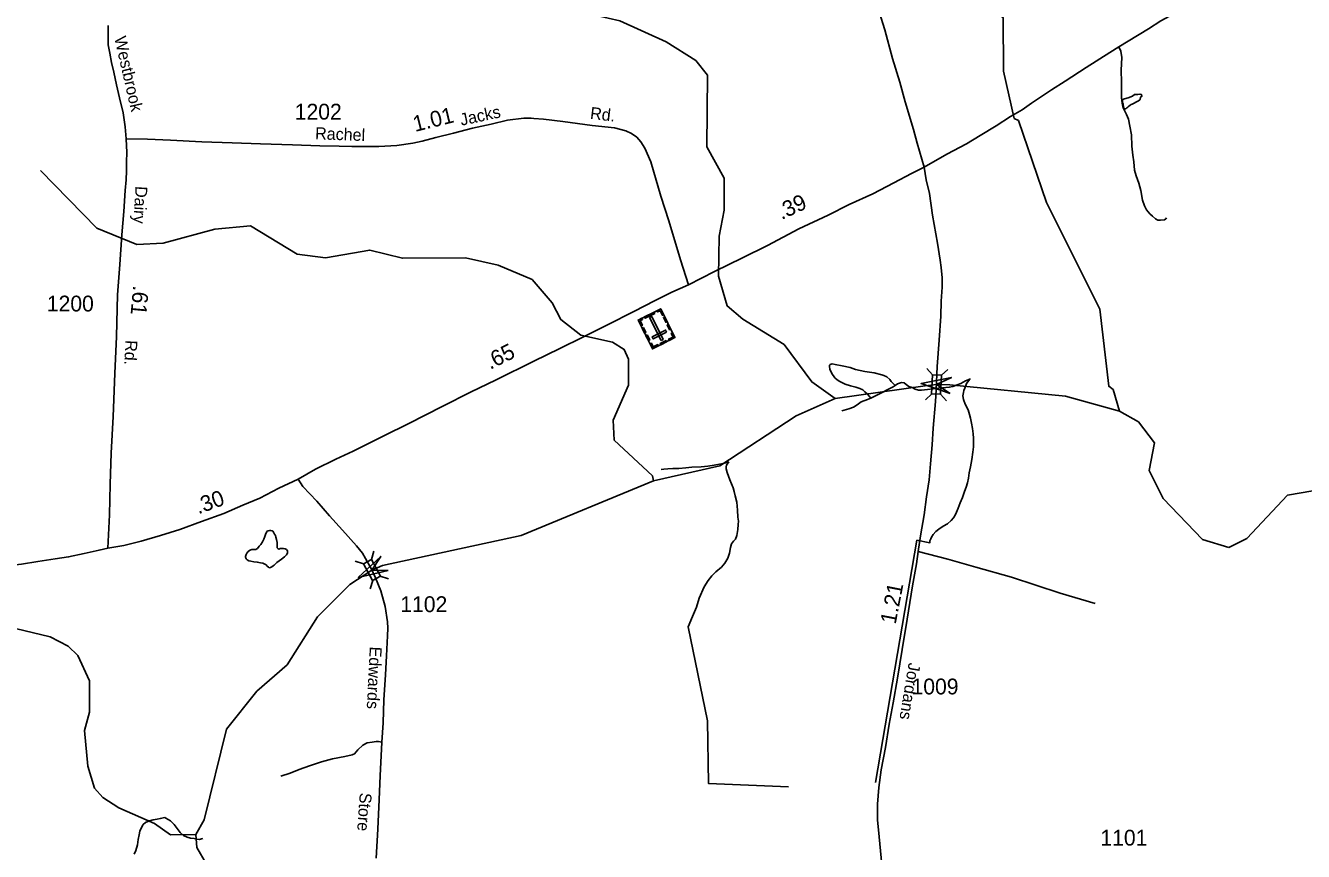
# Model space of a CAD drawing. Extents: x 2206922 to 2357709, y 510027 to 673830.
# Drawn here: x 2214408 to 2224516, y 553694 to 560227 of the extents above; entities that cross this region are included whole.
import ezdxf

# ---------------------------------------------------------------- set-up
doc = ezdxf.new("R2010")
doc.units = 0
for name, color, linetype in [('Exist Cultural Cemetery CELL', 7, 'Continuous'), ('Exist Hydrographic Creek Single Shore', 7, 'Continuous'), ('Exist Hydrographic Misc Water Feature', 7, 'Continuous'), ('Exist Road Non-System Type 51', 7, 'Continuous'), ('Exist Road Primary US Attributed', 7, 'Continuous'), ('Exist Road Primary US Mileage Hundredths English Label', 7, 'Continuous'), ('Exist Road Secondary Mileage Hundredths English Label', 7, 'Continuous'), ('Exist Road Secondary Structure Standard Bridge Attributed CELL', 7, 'Continuous'), ('Exist Road Secondary Structure Standard Bridge CELL', 7, 'Continuous'), ('Exist Road Secondary Type 51 Attributed', 7, 'Continuous'), ('Exist Road Secondary Type 51 Label', 7, 'Continuous'), ('Exist Road Secondary Type 51 Number Label', 7, 'Continuous')]:
    doc.layers.add(name, color=color, linetype=linetype)

msp = doc.modelspace()

# ---------------------------------------------------------------- linework, layer by layer
at = {"layer": 'Exist Cultural Cemetery CELL'}
for points in [[(2219545, 557758), (2219367, 557669), (2219253, 557897), (2219432, 557986)], [(2219402, 557971), (2219407, 557961), (2219427, 557971), (2219445, 557935), (2219455, 557940), (2219432, 557986)], [(2219283, 557912), (2219288, 557902), (2219269, 557892), (2219287, 557856), (2219277, 557851), (2219253, 557897)], [(2219385, 557950), (2219309, 557912), (2219304, 557922), (2219380, 557960)], [(2219435, 557736), (2219451, 557744), (2219361, 557926), (2219344, 557917)], [(2219463, 557924), (2219482, 557885), (2219472, 557880), (2219453, 557918)], [(2219296, 557838), (2219315, 557799), (2219305, 557794), (2219286, 557832)], [(2219478, 557801), (2219470, 557818), (2219365, 557765), (2219373, 557748)], [(2219493, 557863), (2219512, 557825), (2219502, 557820), (2219483, 557858)], [(2219526, 557797), (2219516, 557792), (2219530, 557763), (2219494, 557745), (2219499, 557735), (2219545, 557758)], [(2219325, 557779), (2219345, 557740), (2219335, 557735), (2219315, 557773)], [(2219348, 557708), (2219358, 557713), (2219372, 557684), (2219409, 557703), (2219414, 557693), (2219367, 557669)], [(2219479, 557725), (2219433, 557702), (2219428, 557712), (2219474, 557735)]]:
    msp.add_lwpolyline(points, close=True, dxfattribs=at)
at = {"layer": 'Exist Hydrographic Creek Single Shore'}
for points in [[(2223061, 557176), (2223010, 557347), (2222976, 557374), (2222906, 557982), (2222483, 558827), (2222262, 559475), (2222229, 559492), (2222143, 559867), (2222140, 560291), (2222115, 560307), (2222063, 560508), (2221970, 560691), (2221715, 561470), (2221680, 561713), (2221671, 561871), (2221646, 561895), (2221448, 562768), (2221212, 563117)], [(2223061, 557176), (2222635, 557296), (2221720, 557385), (2221613, 557386), (2221525, 557378), (2220811, 557277)], [(2223926, 556099), (2224069, 556168), (2224391, 556513), (2224590, 556545), (2225058, 556374), (2225391, 556420), (2225573, 556528), (2225987, 556848), (2226593, 557196), (2226824, 557405)], [(2219375, 556624), (2219899, 556744), (2220504, 557139), (2220811, 557277)], [(2223926, 556099), (2223718, 556162), (2223407, 556486), (2223297, 556708), (2223337, 556927), (2223211, 557091), (2223061, 557176)], [(2215754, 553827), (2215820, 553943), (2215998, 554661), (2216238, 554962), (2216478, 555170), (2216717, 555549), (2216973, 555806), (2217147, 555918), (2217230, 555956), (2218328, 556192), (2219375, 556624)], [(2211696, 554498), (2212025, 554650), (2212828, 555394), (2213144, 555532), (2213584, 555635), (2214001, 555577), (2214327, 555456), (2214602, 555392), (2214744, 555317), (2214820, 555243), (2214913, 555044), (2214914, 554795), (2214874, 554651), (2214901, 554369), (2214952, 554194), (2215019, 554120), (2215145, 554039), (2215429, 553915), (2215554, 553824), (2215754, 553827)], [(2215672, 549578), (2216199, 549646), (2216399, 549724), (2216523, 549800), (2216614, 549959), (2216638, 550116), (2216612, 550198), (2216528, 550282), (2216044, 550495), (2215910, 550576), (2215809, 550769), (2215814, 551202), (2215896, 551311), (2216103, 551511), (2216210, 551705), (2216209, 551912), (2216099, 552160), (2216080, 552544), (2216160, 552930), (2216142, 553147), (2216083, 553302), (2215839, 553592), (2215763, 553725), (2215754, 553827)]]:
    msp.add_lwpolyline(points, dxfattribs=at)
at = {"layer": 'Exist Hydrographic Misc Water Feature'}
for points in [[(2220811, 557277), (2220627, 557408), (2220408, 557705), (2220082, 557905), (2219957, 558009), (2219888, 558243), (2219895, 558561), (2219935, 558767), (2219933, 559020), (2219798, 559268), (2219802, 559833), (2219710, 559949), (2219476, 560098), (2219108, 560263), (2218833, 560328), (2218241, 560323), (2217925, 560353), (2217641, 560470), (2217440, 560608), (2216730, 560872), (2216488, 560995), (2216018, 561441), (2215984, 561497)], [(2223090, 559607), (2223086, 559619), (2223084, 559631), (2223084, 559641), (2223100, 559647), (2223129, 559655), (2223165, 559667), (2223181, 559680), (2223207, 559682), (2223221, 559684), (2223231, 559682), (2223235, 559682), (2223239, 559668), (2223228, 559660), (2223225, 559642), (2223223, 559638), (2223211, 559630), (2223206, 559628), (2223190, 559621), (2223176, 559613), (2223162, 559605), (2223154, 559603), (2223146, 559597), (2223134, 559589), (2223128, 559581), (2223118, 559575), (2223112, 559569), (2223104, 559569), (2223098, 559571), (2223092, 559581), (2223090, 559607)], [(2219375, 556624), (2219366, 556666), (2219064, 556948), (2219055, 557106), (2219178, 557382), (2219177, 557589), (2219143, 557665), (2219051, 557722), (2218800, 557777), (2218641, 557901), (2218574, 558034), (2218414, 558217), (2218147, 558331), (2217888, 558389), (2217389, 558386), (2217130, 558450), (2216780, 558388), (2216555, 558419), (2216187, 558643), (2215904, 558616), (2215497, 558506), (2215289, 558494), (2214971, 558625), (2214527, 559080)], [(2221286, 557379), (2221256, 557411), (2221244, 557427), (2221220, 557447), (2221198, 557459), (2221180, 557465), (2221120, 557480), (2221047, 557490), (2220973, 557507), (2220931, 557521), (2220867, 557535), (2220811, 557546), (2220789, 557550), (2220773, 557546), (2220767, 557540), (2220767, 557530), (2220771, 557508), (2220786, 557474), (2220810, 557440), (2220828, 557424), (2220848, 557412), (2220866, 557403), (2220892, 557391), (2220932, 557377), (2220976, 557365), (2221006, 557356), (2221030, 557344), (2221047, 557330), (2221067, 557312), (2221093, 557278)], [(2221132, 554240), (2221459, 556155), (2221561, 556136), (2221562, 556152), (2221568, 556166), (2221573, 556180), (2221586, 556202), (2221608, 556224), (2221632, 556243), (2221666, 556267), (2221701, 556285), (2221729, 556311), (2221749, 556333), (2221761, 556353), (2221771, 556377), (2221786, 556409), (2221800, 556452), (2221818, 556493), (2221835, 556542), (2221847, 556574), (2221859, 556610), (2221867, 556646), (2221871, 556688), (2221882, 556736), (2221892, 556794), (2221901, 556852), (2221905, 556894), (2221907, 556934), (2221907, 556962), (2221904, 556998), (2221898, 557038), (2221890, 557082), (2221882, 557120), (2221875, 557150), (2221863, 557188), (2221841, 557233), (2221827, 557269), (2221822, 557297), (2221826, 557324), (2221830, 557341), (2221838, 557359), (2221852, 557395), (2221877, 557430), (2221881, 557436)], [(2221286, 557379), (2221306, 557392), (2221338, 557402), (2221358, 557400), (2221374, 557386), (2221396, 557372), (2221420, 557363), (2221444, 557351), (2221470, 557343), (2221496, 557343), (2221542, 557347), (2221588, 557354), (2221628, 557358), (2221662, 557362), (2221714, 557366), (2221744, 557371), (2221778, 557385), (2221806, 557395), (2221842, 557415), (2221877, 557430), (2221881, 557436)], [(2221093, 557278), (2221109, 557286), (2221183, 557323), (2221224, 557345), (2221272, 557369), (2221286, 557379)], [(2220865, 557179), (2220884, 557185), (2220920, 557195), (2220957, 557207), (2220985, 557227), (2221019, 557250), (2221067, 557268), (2221093, 557278)], [(2219436, 556715), (2219458, 556717), (2219489, 556720), (2219529, 556722), (2219575, 556724), (2219631, 556729), (2219678, 556733), (2219751, 556735), (2219805, 556742), (2219855, 556750), (2219925, 556762), (2219971, 556775)], [(2220442, 554205), (2219811, 554231), (2219801, 554728), (2219648, 555471), (2219683, 555551), (2219715, 555626), (2219736, 555698), (2219776, 555788), (2219807, 555836), (2219837, 555874), (2219869, 555906), (2219913, 555943), (2219940, 555975), (2219962, 556013), (2219976, 556053), (2219983, 556099), (2219993, 556127), (2220007, 556147), (2220023, 556163), (2220033, 556192), (2220043, 556240), (2220046, 556279), (2220048, 556306), (2220042, 556339), (2220040, 556393), (2220035, 556457), (2220021, 556507), (2220012, 556541), (2220004, 556569), (2219980, 556633), (2219958, 556691), (2219951, 556719), (2219951, 556735), (2219953, 556749), (2219971, 556775)], [(2216396, 555978), (2216384, 555968), (2216374, 555958), (2216366, 555952), (2216357, 555944), (2216350, 555942), (2216346, 555940), (2216336, 555938), (2216330, 555942), (2216320, 555950), (2216310, 555960), (2216296, 555968), (2216284, 555974), (2216266, 555977), (2216240, 555983), (2216214, 555985), (2216190, 555989), (2216174, 555993), (2216160, 556001), (2216152, 556007), (2216150, 556015), (2216148, 556021), (2216148, 556027), (2216150, 556035), (2216154, 556043), (2216159, 556053), (2216169, 556065), (2216180, 556073), (2216189, 556079), (2216197, 556081), (2216213, 556081), (2216221, 556081), (2216229, 556083), (2216237, 556087), (2216243, 556091), (2216257, 556108), (2216269, 556122), (2216281, 556142), (2216293, 556163), (2216301, 556184), (2216309, 556210), (2216316, 556222), (2216320, 556228), (2216328, 556230), (2216338, 556232), (2216348, 556232), (2216358, 556230), (2216364, 556226), (2216368, 556218), (2216376, 556204), (2216384, 556192), (2216388, 556180), (2216393, 556162), (2216397, 556138), (2216399, 556124), (2216399, 556108), (2216397, 556100), (2216399, 556094), (2216405, 556088), (2216413, 556086), (2216423, 556089), (2216435, 556091), (2216449, 556089), (2216461, 556087), (2216471, 556081), (2216479, 556071), (2216481, 556063), (2216480, 556053), (2216475, 556045), (2216472, 556039), (2216455, 556025), (2216432, 556005), (2216396, 555978)], [(2215268, 553672), (2215280, 553700), (2215292, 553746), (2215299, 553788), (2215307, 553826), (2215313, 553854), (2215321, 553878), (2215337, 553906), (2215357, 553922), (2215388, 553935), (2215418, 553943), (2215449, 553949), (2215473, 553953), (2215510, 553961)], [(2215510, 553961), (2215518, 553957), (2215553, 553935), (2215583, 553906), (2215607, 553874), (2215631, 553844), (2215657, 553820), (2215687, 553806), (2215713, 553799), (2215741, 553795), (2215762, 553791), (2215782, 553789), (2215809, 553797)]]:
    msp.add_lwpolyline(points, dxfattribs=at)
at = {"layer": 'Exist Road Non-System Type 51'}
for points in [[(2223056, 560057), (2223073, 560024), (2223080, 559974), (2223075, 559874), (2223076, 559779), (2223076, 559686), (2223077, 559656), (2223080, 559633), (2223082, 559612), (2223087, 559587), (2223093, 559571), (2223116, 559523), (2223132, 559486), (2223144, 559432), (2223155, 559363), (2223160, 559273), (2223167, 559201), (2223174, 559148), (2223181, 559082), (2223192, 559038), (2223213, 558981), (2223231, 558923), (2223244, 558846), (2223259, 558801), (2223276, 558769), (2223300, 558738), (2223322, 558719), (2223346, 558697), (2223364, 558688), (2223386, 558687), (2223416, 558690), (2223428, 558699), (2223433, 558706)], [(2221468, 556067), (2221702, 556006), (2221926, 555942), (2222207, 555862), (2222591, 555738), (2222868, 555654)], [(2217227, 554557), (2217199, 554564), (2217180, 554563), (2217150, 554559), (2217110, 554553), (2217075, 554535), (2217035, 554498), (2217010, 554467), (2216992, 554458), (2216933, 554444), (2216837, 554427), (2216749, 554403), (2216653, 554370), (2216571, 554343), (2216501, 554312), (2216428, 554288)]]:
    msp.add_lwpolyline(points, dxfattribs=at)
at = {"layer": 'Exist Road Primary US Attributed'}
for points in [[(2221517, 559106), (2221695, 559208), (2221851, 559292), (2221960, 559358), (2222086, 559434), (2222198, 559507), (2222291, 559560), (2222366, 559613), (2222435, 559660), (2222524, 559718), (2222632, 559786), (2222798, 559896), (2222986, 560013), (2223056, 560057), (2223130, 560104), (2223290, 560201), (2223388, 560265), (2223456, 560302), (2223585, 560379), (2223708, 560443), (2223816, 560487), (2223892, 560509), (2224440, 560752), (2225070, 560997)], [(2219652, 558177), (2219858, 558281), (2220078, 558388), (2220278, 558487), (2220525, 558618), (2220756, 558726), (2220923, 558812), (2221109, 558896), (2221277, 558983), (2221417, 559056), (2221517, 559106)], [(2216564, 556638), (2216700, 556717), (2216861, 556796), (2216999, 556860), (2217248, 556984), (2217434, 557077), (2217708, 557216), (2217927, 557326), (2218131, 557423), (2218429, 557571), (2218633, 557673), (2218815, 557761), (2219011, 557860), (2219219, 557965), (2219387, 558051), (2219520, 558118), (2219652, 558177)], [(2215059, 556092), (2215184, 556115), (2215321, 556148), (2215476, 556193), (2215627, 556240), (2215799, 556303), (2215977, 556367), (2216126, 556433), (2216260, 556489), (2216411, 556567), (2216564, 556638)], [(2213142, 555805), (2213284, 555822), (2213488, 555848), (2213712, 555877), (2213974, 555912), (2214205, 555948), (2214376, 555967), (2214506, 555986), (2214641, 556007), (2214748, 556023), (2214872, 556051), (2214990, 556078), (2215059, 556092)]]:
    msp.add_lwpolyline(points, dxfattribs=at)
at = {"layer": 'Exist Road Secondary Structure Standard Bridge Attributed CELL'}
for points in [[(2221723, 557316), (2221492, 557394), (2221731, 557442), (2221613, 557386)], [(2217277, 555916), (2217040, 555861), (2217218, 556027), (2217147, 555918)]]:
    msp.add_lwpolyline(points, close=True, dxfattribs=at)
at = {"layer": 'Exist Road Secondary Structure Standard Bridge CELL'}
for p, q in [((2221536, 557515), (2221583, 557464)), ((2221704, 557507), (2221653, 557461)), ((2221577, 557313), (2221526, 557267)), ((2221646, 557310), (2221692, 557259)), ((2217163, 556069), (2217143, 556003)), ((2217015, 555989), (2217081, 555969)), ((2217214, 555870), (2217280, 555850)), ((2217154, 555837), (2217134, 555771))]:
    msp.add_line(p, q, dxfattribs=at)
for points in [[(2221653, 557461), (2221646, 557310), (2221575, 557313), (2221583, 557464)], [(2217143, 556003), (2217215, 555870), (2217152, 555836), (2217081, 555969)]]:
    msp.add_lwpolyline(points, close=True, dxfattribs=at)
at = {"layer": 'Exist Road Secondary Type 51 Attributed'}
for points in [[(2221517, 559106), (2221460, 559296), (2221432, 559404), (2221366, 559624), (2221324, 559779), (2221266, 559966), (2221204, 560192), (2221161, 560336)], [(2215203, 559331), (2215197, 559425), (2215179, 559536), (2215152, 559655), (2215126, 559758), (2215105, 559859), (2215088, 559934), (2215074, 560009), (2215062, 560074), (2215060, 560109), (2215060, 560175), (2215062, 560228)], [(2219652, 558177), (2219588, 558373), (2219496, 558682), (2219434, 558878), (2219355, 559148), (2219307, 559258), (2219276, 559308), (2219244, 559343), (2219202, 559373), (2219157, 559394), (2219067, 559417), (2218889, 559437), (2218657, 559468), (2218505, 559487), (2218429, 559492), (2218407, 559494), (2218348, 559495), (2218221, 559478), (2218090, 559447), (2217944, 559414), (2217793, 559375), (2217652, 559342), (2217545, 559313), (2217471, 559296), (2217344, 559277), (2217203, 559270), (2216990, 559270), (2216889, 559272), (2216735, 559275), (2216519, 559283), (2216267, 559291), (2216041, 559298), (2215803, 559306), (2215555, 559320), (2215373, 559327), (2215203, 559331)], [(2215059, 556092), (2215071, 556357), (2215078, 556599), (2215086, 556844), (2215101, 557135), (2215113, 557475), (2215126, 557768), (2215136, 558097), (2215154, 558337), (2215170, 558572), (2215185, 558755), (2215195, 558922), (2215203, 559006), (2215205, 559077), (2215207, 559149), (2215208, 559223), (2215203, 559331)], [(2221610, 557344), (2221620, 557530), (2221635, 557738), (2221647, 557927), (2221650, 558047), (2221659, 558156), (2221659, 558232), (2221651, 558312), (2221643, 558372), (2221622, 558505), (2221583, 558726), (2221557, 558898), (2221532, 559006), (2221517, 559106)], [(2221181, 553589), (2221161, 553809), (2221148, 553945), (2221146, 554000), (2221146, 554068), (2221157, 554199), (2221177, 554338), (2221209, 554515), (2221240, 554700), (2221270, 554870), (2221306, 555065), (2221342, 555290), (2221381, 555531), (2221423, 555796), (2221455, 555969), (2221468, 556067), (2221487, 556191), (2221516, 556357), (2221535, 556498), (2221555, 556633), (2221566, 556759), (2221580, 556910), (2221587, 557042), (2221606, 557254), (2221610, 557344)], [(2216564, 556638), (2216601, 556581), (2216713, 556464), (2216811, 556348), (2216915, 556235), (2217026, 556112), (2217073, 556052), (2217097, 556011), (2217141, 555933), (2217158, 555898)], [(2217158, 555898), (2217176, 555859), (2217219, 555755), (2217253, 555630), (2217270, 555509), (2217273, 555460), (2217272, 555399), (2217262, 555241), (2217255, 555092), (2217243, 554893), (2217236, 554710), (2217227, 554557), (2217212, 554291), (2217205, 554104), (2217194, 553870), (2217182, 553640)]]:
    msp.add_lwpolyline(points, dxfattribs=at)

# ---------------------------------------------------------------- texts
at = {"layer": 'Exist Road Primary US Mileage Hundredths English Label'}
for s, rotation, p in [('.39', 24.9231, (2220388, 558688)), ('.65', 26.3879, (2218083, 557503)), ('.30', 19.8653, (2215774, 556360))]:
    msp.add_text(s, height=125, rotation=rotation, dxfattribs=at).set_placement(p)
at = {"layer": 'Exist Road Secondary Mileage Hundredths English Label'}
for s, rotation, p in [('1.01', 13.8552, (2217489, 559385)), ('.61', 264.6815, (2215260, 558173)), ('1.21', 78.9541, (2221290, 555486))]:
    msp.add_text(s, height=125, rotation=rotation, dxfattribs=at).set_placement(p)
at = {"layer": 'Exist Road Secondary Type 51 Label'}
for s, rotation, p in [('Westbrook', 282.9185, (2215109, 560130)), ('Jacks', 12.0954, (2217855, 559434)), ('Rd.', 353.3385, (2218870, 559489)), ('Rachel', 357.8185, (2216697, 559328)), ('Dairy', 266.4878, (2215278, 558959)), ('Rd.', 267.1435, (2215198, 557740)), ('Edwards', 267.1804, (2217131, 555316)), ('Jordans', 260.6236, (2221394, 555190)), ('Store', 266.0518, (2217052, 554160))]:
    msp.add_text(s, height=95, rotation=rotation, dxfattribs=at).set_placement(p)
at = {"layer": 'Exist Road Secondary Type 51 Number Label'}
for s, p in [('1202', (2216537, 559483)), ('1200', (2214576, 557965)), ('1102', (2217372, 555587)), ('1009', (2221416, 554936)), ('1101', (2222910, 553740))]:
    msp.add_text(s, height=125, dxfattribs=at).set_placement(p)

doc.saveas('drawing.dxf')
